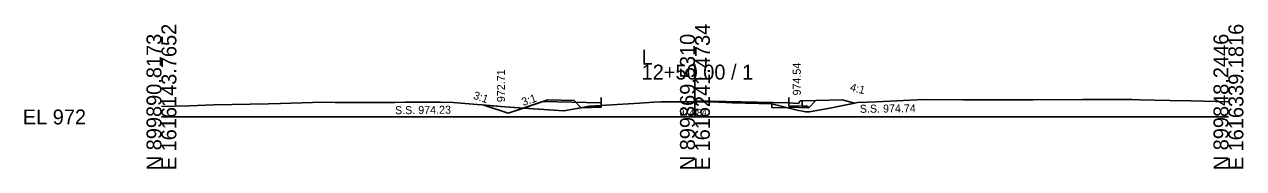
# Model space of a CAD drawing. Extents: x 1009 to 7438, y -1586 to 7964.
# Drawn here: x 1009.2 to 1237.7, y 414 to 441.1 of the extents above; entities that cross this region are included whole.
import ezdxf

# ---------------------------------------------------------------- set-up
doc = ezdxf.new("R2010")
doc.units = 0
for name, color, linetype in [('Exist Cross Section Cell', 7, 'Continuous'), ('Exist XS Center Line Elevation Label', 7, 'Continuous'), ('Exist XS Ground Line', 7, 'Continuous'), ('Prop XS Dump Level', 7, 'Continuous'), ('Prop XS Earthwork Shape', 7, 'Continuous'), ('Prop XS EOT Tick Mark', 7, 'Continuous'), ('Prop XS Finish Grade', 7, 'Continuous'), ('Prop XS Finish Grade CurbGutter', 7, 'Continuous'), ('Prop XS Finish Grade Earthwork', 7, 'Continuous'), ('Prop XS Finish Grade Pavement', 7, 'Continuous'), ('Prop XS Hydro Elevations', 7, 'Continuous'), ('Prop XS Pvmt Edge Slope', 7, 'Continuous'), ('Prop XS SE Text', 7, 'Continuous'), ('Prop XS Side Slope Text', 7, 'Continuous'), ('Prop XS SS Elevation Text', 7, 'Continuous'), ('Prop XS Subgrade CurbGutter', 7, 'Continuous'), ('Prop XS Subgrade Earthwork', 7, 'Continuous')]:
    doc.layers.add(name, color=color, linetype=linetype)

msp = doc.modelspace()

# ---------------------------------------------------------------- linework, layer by layer
at = {"layer": 'Exist Cross Section Cell'}
for p, q in [((1134.89, 423.73), (1134.89, 433.55)), ((1034.89, 423.73), (1134.89, 423.73)), ((1134.89, 423.73), (1234.89, 423.73))]:
    msp.add_line(p, q, dxfattribs=at)
at = {"layer": 'Exist XS Ground Line'}
for p, q in [((1034.89, 425.68), (1040.09, 425.85)), ((1040.09, 425.85), (1044.74, 426.01)), ((1044.74, 426.01), (1054.98, 426.21)), ((1054.98, 426.21), (1057.21, 426.27)), ((1057.21, 426.27), (1065.21, 426.48)), ((1065.21, 426.48), (1067.44, 426.45)), ((1067.44, 426.45), (1078.65, 426.46)), ((1078.65, 426.46), (1080.59, 426.5)), ((1080.59, 426.5), (1082.74, 426.53)), ((1082.74, 426.53), (1087.19, 426.51)), ((1087.19, 426.51), (1089.55, 426.45)), ((1089.55, 426.45), (1094.04, 426.06)), ((1094.04, 426.06), (1095.05, 425.98)), ((1095.05, 425.98), (1099.23, 425.64)), ((1099.23, 425.64), (1110.33, 424.85)), ((1110.33, 424.85), (1112.78, 425.31)), ((1112.78, 425.31), (1115.15, 425.77)), ((1115.15, 425.77), (1124.52, 426.35)), ((1124.52, 426.35), (1127.21, 426.52)), ((1127.21, 426.52), (1128.51, 426.54)), ((1128.51, 426.54), (1133.22, 426.59)), ((1133.22, 426.59), (1134.89, 426.57)), ((1134.89, 426.57), (1138.09, 426.54)), ((1138.09, 426.54), (1141.94, 426.41)), ((1141.94, 426.41), (1149.32, 426.2)), ((1149.32, 426.2), (1154.27, 424.97)), ((1158.06, 425.02), (1160.16, 425.41)), ((1160.16, 425.41), (1165.36, 426.42)), ((1165.36, 426.42), (1168.95, 426.59)), ((1168.95, 426.59), (1177.8, 427)), ((1177.8, 427), (1185.21, 426.95)), ((1185.21, 426.95), (1188.03, 426.95)), ((1188.03, 426.95), (1198.28, 426.95)), ((1198.28, 426.95), (1207.59, 426.98)), ((1207.59, 426.98), (1209.61, 426.99)), ((1209.61, 426.99), (1216.8, 427)), ((1216.8, 427), (1218.2, 426.97)), ((1218.2, 426.97), (1223.93, 426.84)), ((1223.93, 426.84), (1227.87, 426.74)), ((1227.87, 426.74), (1234.89, 426.59)), ((1154.27, 424.97), (1155.12, 424.8)), ((1155.12, 424.8), (1155.63, 424.7)), ((1155.63, 424.7), (1156.38, 424.7)), ((1156.38, 424.7), (1158.06, 425.02))]:
    msp.add_line(p, q, dxfattribs=at)
at = {"layer": 'Prop XS Dump Level'}
for p, q in [((1143.64, 426.55), (1134.89, 426.73)), ((1134.89, 426.73), (1143.64, 426.55))]:
    msp.add_line(p, q, dxfattribs=at)
at = {"layer": 'Prop XS Earthwork Shape'}
for points in [[(1095.33, 425.96), (1099.23, 425.64), (1102.74, 425.39), (1099.88, 424.44)], [(1102.74, 425.39), (1110.33, 424.85), (1112.78, 425.31), (1113.62, 425.47), (1113.56, 425.47), (1112.22, 426.81), (1107.31, 426.92)], [(1113.62, 425.47), (1115.05, 425.75), (1117.31, 425.8), (1117.31, 425.55)], [(1115.05, 425.75), (1115.15, 425.77), (1117.31, 425.9), (1117.31, 425.8)], [(1149.29, 426.2), (1149.32, 426.2), (1152.28, 425.46), (1149.29, 425.52)], [(1158.06, 425.02), (1160.16, 425.41), (1164.86, 426.32), (1162.48, 426.92), (1157.57, 426.81), (1156.23, 425.47), (1152.48, 425.55), (1152.48, 425.46), (1152.28, 425.46), (1154.27, 424.97), (1155.12, 424.8), (1155.63, 424.7), (1156.38, 424.7)]]:
    msp.add_lwpolyline(points, close=True, dxfattribs=at)
at = {"layer": 'Prop XS EOT Tick Mark'}
for p, q in [((1117.31, 426.38), (1117.31, 427.38)), ((1152.48, 426.38), (1152.48, 427.38))]:
    msp.add_line(p, q, dxfattribs=at)
at = {"layer": 'Prop XS Finish Grade'}
msp.add_line((1154.98, 426.76), (1157.57, 426.81), dxfattribs=at)
at = {"layer": 'Prop XS Finish Grade CurbGutter'}
for p, q in [((1152.48, 426.38), (1154.23, 426.27)), ((1154.23, 426.27), (1154.35, 426.3)), ((1154.35, 426.3), (1154.44, 426.39)), ((1154.44, 426.39), (1154.51, 426.64)), ((1154.51, 426.64), (1154.6, 426.73)), ((1154.73, 426.76), (1154.6, 426.73)), ((1154.98, 426.76), (1154.73, 426.76))]:
    msp.add_line(p, q, dxfattribs=at)
at = {"layer": 'Prop XS Finish Grade Earthwork'}
for p, q in [((1099.88, 424.44), (1095.33, 425.96)), ((1106.38, 426.61), (1099.88, 424.44)), ((1117.31, 426.38), (1106.38, 426.61)), ((1117.32, 425.9), (1117.31, 426.38)), ((1157.57, 426.81), (1162.48, 426.92)), ((1162.48, 426.92), (1164.86, 426.32))]:
    msp.add_line(p, q, dxfattribs=at)
at = {"layer": 'Prop XS Finish Grade Pavement'}
for p, q in [((1134.89, 426.73), (1143.64, 426.55)), ((1143.64, 426.55), (1152.48, 426.38))]:
    msp.add_line(p, q, dxfattribs=at)
at = {"layer": 'Prop XS Pvmt Edge Slope'}
for p, q in [((1154.98, 425.75), (1155.98, 425.73)), ((1155.98, 425.73), (1156.23, 425.47))]:
    msp.add_line(p, q, dxfattribs=at)
at = {"layer": 'Prop XS Subgrade CurbGutter'}
for p, q in [((1152.48, 426.38), (1152.48, 425.8)), ((1152.48, 425.8), (1154.98, 425.75)), ((1154.98, 425.75), (1154.98, 426.76))]:
    msp.add_line(p, q, dxfattribs=at)
at = {"layer": 'Prop XS Subgrade Earthwork'}
for p, q in [((1149.29, 425.52), (1149.29, 426.2)), ((1149.29, 425.52), (1152.48, 425.46)), ((1152.48, 425.46), (1152.48, 425.55)), ((1152.48, 425.55), (1156.23, 425.47)), ((1156.23, 425.47), (1157.57, 426.81))]:
    msp.add_line(p, q, dxfattribs=at)

# ---------------------------------------------------------------- texts
at = {"layer": 'Exist Cross Section Cell'}
for s, p in [('E 1616241.4734', (1137.69, 413.73)), ('N 899890.8173', (1034.89, 413.73)), ('E 1616143.7652', (1037.69, 413.73)), ('N 899869.5310', (1134.89, 413.73)), ('N 899848.2446', (1234.89, 413.73)), ('E 1616339.1816', (1237.69, 413.73))]:
    msp.add_text(s, height=2.8, rotation=90, dxfattribs=at).set_placement(p)
for s, p in [('L', (1124.89, 433.55)), ('12+50.00 / 1', (1124.89, 430.75)), ('EL 972', (1008.89, 422.33))]:
    msp.add_text(s, height=2.8, dxfattribs=at).set_placement(p)
at = {"layer": 'Exist XS Center Line Elevation Label'}
msp.add_text('974.84', height=1.25, dxfattribs=at).set_placement((1131.99, 423.95))
at = {"layer": 'Prop XS Dump Level'}
for p in [(1115.21, 425.48), (1149.29, 425.9)]:
    msp.add_text('Eop', height=0.3, dxfattribs=at).set_placement(p)
at = {"layer": 'Prop XS Hydro Elevations'}
for s, p in [('972.71', (1099.29, 426.51)), ('974.54', (1154.73, 427.76))]:
    msp.add_text(s, height=1.5, rotation=90, dxfattribs=at).set_placement(p)
at = {"layer": 'Prop XS SE Text'}
for rotation, p in [(341.5651, (1093.22, 427.17)), (18.4349, (1102.7, 425.78))]:
    msp.add_text('3:1', height=1.5, rotation=rotation, dxfattribs=at).set_placement(p)
at = {"layer": 'Prop XS Side Slope Text'}
msp.add_text('4:1', height=1.5, rotation=345.9638, dxfattribs=at).set_placement((1163.86, 428.66))
at = {"layer": 'Prop XS SS Elevation Text'}
for s, p in [('S.S. 974.23', (1078.68, 424.24)), ('S.S. 974.74', (1165.8, 424.51))]:
    msp.add_text(s, height=1.5, rotation=0.5729, dxfattribs=at).set_placement(p)

doc.saveas('drawing.dxf')
